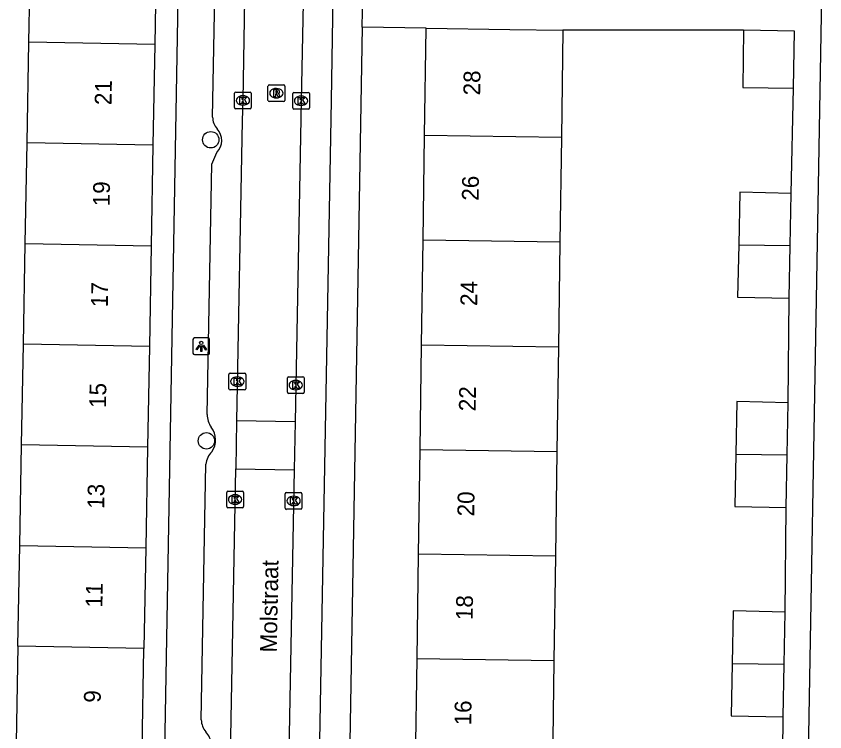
# Model space of a CAD drawing. Extents: x 160026 to 161302, y 384757 to 385701.
# Drawn here: x 160719.58 to 160767.81, y 385050.88 to 385093.54 of the extents above; entities that cross this region are included whole.
import ezdxf

# ---------------------------------------------------------------- set-up
doc = ezdxf.new("R2010")
doc.units = 0
for name, color, linetype in [('IMGEO_Boom', 7, 'Continuous'), ('IMGEO_Kolk', 7, 'Continuous'), ('IMGEO_Lichtpunt', 7, 'Continuous'), ('IMGEO_Openbare_ruimte_label', 7, 'Continuous'), ('IMGEO_Pand', 7, 'Continuous'), ('IMGEO_Pand_nummerreeks', 7, 'Continuous'), ('IMGEO_Rijbaan_lokaal_open', 7, 'Continuous'), ('IMGEO_Rioolput', 7, 'Continuous'), ('IMGEO_Voetpad_open', 7, 'Continuous')]:
    doc.layers.add(name, color=color, linetype=linetype)

msp = doc.modelspace()

# ---------------------------------------------------------------- linework, layer by layer
at = {"layer": 'IMGEO_Boom'}
for centre in [(160731.185, 385086.174), (160730.926, 385068.229)]:
    msp.add_circle(centre, 0.489, dxfattribs=at)
at = {"layer": 'IMGEO_Kolk'}
for p, q in [((160732.599, 385088.094), (160732.599, 385088.946)), ((160732.674, 385089.02), (160733.526, 385089.02)), ((160733.6, 385088.946), (160733.6, 385088.094)), ((160736.147, 385089.001), (160736.999, 385089.001)), ((160733.087, 385088.8), (160733.112, 385088.8)), ((160736.072, 385088.075), (160736.072, 385088.927)), ((160736.56, 385088.781), (160736.585, 385088.781)), ((160737.073, 385088.927), (160737.073, 385088.075)), ((160733.526, 385088.02), (160732.674, 385088.02)), ((160733.11, 385088.24), (160733.085, 385088.24)), ((160736.999, 385088.001), (160736.147, 385088.001)), ((160736.583, 385088.221), (160736.558, 385088.221)), ((160732.269, 385071.334), (160732.269, 385072.186)), ((160732.344, 385072.26), (160733.196, 385072.26)), ((160733.27, 385072.186), (160733.27, 385071.334)), ((160732.757, 385072.04), (160732.782, 385072.04)), ((160735.754, 385071.125), (160735.754, 385071.977)), ((160735.829, 385072.051), (160736.681, 385072.051)), ((160736.242, 385071.831), (160736.267, 385071.831)), ((160736.755, 385071.977), (160736.755, 385071.125)), ((160733.196, 385071.26), (160732.344, 385071.26)), ((160732.78, 385071.48), (160732.755, 385071.48)), ((160736.265, 385071.271), (160736.24, 385071.271)), ((160736.681, 385071.051), (160735.829, 385071.051)), ((160732.138, 385064.307), (160732.138, 385065.159)), ((160732.213, 385065.233), (160733.065, 385065.233)), ((160732.626, 385065.013), (160732.651, 385065.013)), ((160733.139, 385065.159), (160733.139, 385064.307)), ((160735.624, 385064.22), (160735.624, 385065.072)), ((160735.699, 385065.146), (160736.551, 385065.146)), ((160736.112, 385064.926), (160736.137, 385064.926)), ((160736.625, 385065.072), (160736.625, 385064.22)), ((160732.649, 385064.453), (160732.624, 385064.453)), ((160736.135, 385064.366), (160736.11, 385064.366)), ((160733.065, 385064.233), (160732.213, 385064.233)), ((160736.551, 385064.146), (160735.699, 385064.146))]:
    msp.add_line(p, q, dxfattribs=at)
for points in [[(160732.599, 385088.094), (160732.599, 385088.946)], [(160732.674, 385089.02), (160733.526, 385089.02)], [(160733.6, 385088.946), (160733.6, 385088.094)], [(160736.147, 385089.001), (160736.999, 385089.001)], [(160732.92, 385088.72), (160733.043, 385088.72), (160733.043, 385088.569), (160733.173, 385088.72), (160733.337, 385088.72), (160733.191, 385088.569), (160733.344, 385088.32), (160733.192, 385088.32), (160733.107, 385088.484), (160733.043, 385088.417), (160733.043, 385088.32), (160732.92, 385088.32), (160732.92, 385088.72)], [(160736.072, 385088.075), (160736.072, 385088.927)], [(160736.393, 385088.701), (160736.516, 385088.701), (160736.516, 385088.55), (160736.646, 385088.701), (160736.81, 385088.701), (160736.664, 385088.55), (160736.817, 385088.301), (160736.665, 385088.301), (160736.58, 385088.465), (160736.516, 385088.398), (160736.516, 385088.301), (160736.393, 385088.301), (160736.393, 385088.701)], [(160737.073, 385088.927), (160737.073, 385088.075)], [(160733.526, 385088.02), (160732.674, 385088.02)], [(160736.999, 385088.001), (160736.147, 385088.001)], [(160732.269, 385071.334), (160732.269, 385072.186)], [(160732.344, 385072.26), (160733.196, 385072.26)], [(160733.27, 385072.186), (160733.27, 385071.334)], [(160732.59, 385071.96), (160732.713, 385071.96), (160732.713, 385071.809), (160732.843, 385071.96), (160733.007, 385071.96), (160732.861, 385071.809), (160733.014, 385071.56), (160732.862, 385071.56), (160732.777, 385071.724), (160732.713, 385071.657), (160732.713, 385071.56), (160732.59, 385071.56), (160732.59, 385071.96)], [(160735.754, 385071.125), (160735.754, 385071.977)], [(160735.829, 385072.051), (160736.681, 385072.051)], [(160736.075, 385071.751), (160736.198, 385071.751), (160736.198, 385071.6), (160736.328, 385071.751), (160736.492, 385071.751), (160736.346, 385071.6), (160736.499, 385071.351), (160736.347, 385071.351), (160736.262, 385071.515), (160736.198, 385071.448), (160736.198, 385071.351), (160736.075, 385071.351), (160736.075, 385071.751)], [(160736.755, 385071.977), (160736.755, 385071.125)], [(160733.196, 385071.26), (160732.344, 385071.26)], [(160736.681, 385071.051), (160735.829, 385071.051)], [(160732.138, 385064.307), (160732.138, 385065.159)], [(160732.213, 385065.233), (160733.065, 385065.233)], [(160732.459, 385064.933), (160732.582, 385064.933), (160732.582, 385064.782), (160732.712, 385064.933), (160732.876, 385064.933), (160732.73, 385064.782), (160732.883, 385064.533), (160732.731, 385064.533), (160732.646, 385064.697), (160732.582, 385064.63), (160732.582, 385064.533), (160732.459, 385064.533), (160732.459, 385064.933)], [(160733.139, 385065.159), (160733.139, 385064.307)], [(160735.624, 385064.22), (160735.624, 385065.072)], [(160735.699, 385065.146), (160736.551, 385065.146)], [(160735.945, 385064.846), (160736.068, 385064.846), (160736.068, 385064.695), (160736.198, 385064.846), (160736.362, 385064.846), (160736.216, 385064.695), (160736.369, 385064.446), (160736.217, 385064.446), (160736.132, 385064.61), (160736.068, 385064.543), (160736.068, 385064.446), (160735.945, 385064.446), (160735.945, 385064.846)], [(160736.625, 385065.072), (160736.625, 385064.22)], [(160733.065, 385064.233), (160732.213, 385064.233)], [(160736.551, 385064.146), (160735.699, 385064.146)]]:
    msp.add_lwpolyline(points, dxfattribs=at)
for centre, start, end in [((160732.676, 385088.944), 91.552, 178.448), ((160732.676, 385088.944), 91.552, 178.448), ((160733.524, 385088.944), 1.552, 88.448), ((160733.524, 385088.944), 1.552, 88.448), ((160736.149, 385088.925), 91.552, 178.448), ((160736.149, 385088.925), 91.552, 178.448), ((160736.997, 385088.925), 1.552, 88.448), ((160736.997, 385088.925), 1.552, 88.448), ((160732.676, 385088.096), 181.552, 268.448), ((160732.676, 385088.096), 181.552, 268.448), ((160733.524, 385088.096), 271.552, 358.448), ((160733.524, 385088.096), 271.552, 358.448), ((160736.149, 385088.077), 181.552, 268.448), ((160736.149, 385088.077), 181.552, 268.448), ((160736.997, 385088.077), 271.552, 358.448), ((160736.997, 385088.077), 271.552, 358.448), ((160732.346, 385072.184), 91.552, 178.448), ((160732.346, 385072.184), 91.552, 178.448), ((160733.194, 385072.184), 1.552, 88.448), ((160733.194, 385072.184), 1.552, 88.448), ((160735.831, 385071.975), 91.552, 178.448), ((160735.831, 385071.975), 91.552, 178.448), ((160736.679, 385071.975), 1.552, 88.448), ((160736.679, 385071.975), 1.552, 88.448), ((160732.346, 385071.336), 181.552, 268.448), ((160732.346, 385071.336), 181.552, 268.448), ((160733.194, 385071.336), 271.552, 358.448), ((160733.194, 385071.336), 271.552, 358.448), ((160735.831, 385071.127), 181.552, 268.448), ((160735.831, 385071.127), 181.552, 268.448), ((160736.679, 385071.127), 271.552, 358.448), ((160736.679, 385071.127), 271.552, 358.448), ((160732.215, 385065.157), 91.552, 178.448), ((160732.215, 385065.157), 91.552, 178.448), ((160733.063, 385065.157), 1.552, 88.448), ((160733.063, 385065.157), 1.552, 88.448), ((160735.701, 385065.07), 91.552, 178.448), ((160735.701, 385065.07), 91.552, 178.448), ((160736.549, 385065.07), 1.552, 88.448), ((160736.549, 385065.07), 1.552, 88.448), ((160732.215, 385064.309), 181.552, 268.448), ((160732.215, 385064.309), 181.552, 268.448), ((160733.063, 385064.309), 271.552, 358.448), ((160733.063, 385064.309), 271.552, 358.448), ((160735.701, 385064.222), 181.552, 268.448), ((160735.701, 385064.222), 181.552, 268.448), ((160736.549, 385064.222), 271.552, 358.448), ((160736.549, 385064.222), 271.552, 358.448)]:
    msp.add_arc(centre, 0.0765, start, end, dxfattribs=at)
for centre, major_axis, ratio, start_param, end_param in [((160733.086, 385088.52), (-0.387, 0.002), 0.722429, 4.712389, 7.853982), ((160733.111, 385088.52), (-0.39, 0.002), 0.717154, 1.570796, 4.712389), ((160736.559, 385088.501), (-0.387, 0.002), 0.722429, 4.712389, 7.853982), ((160736.584, 385088.501), (-0.39, 0.002), 0.717154, 1.570796, 4.712389), ((160732.756, 385071.76), (-0.387, 0.002), 0.722429, 4.712389, 7.853982), ((160732.781, 385071.76), (-0.39, 0.002), 0.717154, 1.570796, 4.712389), ((160736.241, 385071.551), (-0.387, 0.002), 0.722429, 4.712389, 7.853982), ((160736.266, 385071.551), (-0.39, 0.002), 0.717154, 1.570796, 4.712389), ((160732.625, 385064.733), (-0.387, 0.002), 0.722429, 4.712389, 7.853982), ((160732.65, 385064.733), (-0.39, 0.002), 0.717154, 1.570796, 4.712389), ((160736.111, 385064.646), (-0.387, 0.002), 0.722429, 4.712389, 7.853982), ((160736.136, 385064.646), (-0.39, 0.002), 0.717154, 1.570796, 4.712389)]:
    msp.add_ellipse(centre, major_axis=major_axis, ratio=ratio, start_param=start_param, end_param=end_param, dxfattribs=at)
at = {"layer": 'IMGEO_Lichtpunt'}
for p, q in [((160730.12, 385074.27), (160730.12, 385073.463)), ((160730.12, 385074.27), (160730.12, 385073.463)), ((160731.022, 385074.365), (160730.214, 385074.365)), ((160731.022, 385074.365), (160730.214, 385074.365)), ((160731.116, 385073.463), (160731.116, 385074.27)), ((160731.116, 385073.463), (160731.116, 385074.27)), ((160730.214, 385073.369), (160731.022, 385073.369)), ((160730.214, 385073.369), (160731.022, 385073.369))]:
    msp.add_line(p, q, dxfattribs=at)
for points in [[(160730.494, 385073.934), (160730.533, 385073.906), (160730.345, 385073.644), (160730.307, 385073.671), (160730.494, 385073.934)], [(160730.596, 385073.886), (160730.643, 385073.886), (160730.643, 385073.564), (160730.596, 385073.564), (160730.596, 385073.886)], [(160730.706, 385073.906), (160730.744, 385073.933), (160730.931, 385073.671), (160730.892, 385073.643), (160730.706, 385073.906)]]:
    msp.add_lwpolyline(points, dxfattribs=at)
msp.add_circle((160730.619, 385074.068), 0.0994, dxfattribs=at)
for centre, start, end in [((160730.214, 385074.27), 90, 180), ((160730.214, 385074.27), 90, 180), ((160731.022, 385074.27), 0, 90), ((160731.022, 385074.27), 0, 90), ((160730.214, 385073.463), 180, 270), ((160730.214, 385073.463), 180, 270), ((160731.022, 385073.463), 270, 0), ((160731.022, 385073.463), 270, 360)]:
    msp.add_arc(centre, 0.0946, start, end, dxfattribs=at)
at = {"layer": 'IMGEO_Pand'}
for points in [[(160720.336, 385091.989), (160720.446, 385098.051)], [(160727.958, 385097.915), (160727.848, 385091.853)], [(160743.937, 385086.427), (160744.028, 385092.821)], [(160744.028, 385092.821), (160749.028, 385092.751), (160752.188, 385092.706)], [(160752.188, 385092.706), (160752.097, 385086.311)], [(160762.97, 385092.7), (160762.918, 385089.293), (160765.949, 385089.247)], [(160765.949, 385089.247), (160766.002, 385092.654), (160762.97, 385092.7)], [(160720.227, 385085.99), (160720.336, 385091.989)], [(160727.848, 385091.853), (160720.336, 385091.989)], [(160727.848, 385091.853), (160727.739, 385085.854)], [(160743.849, 385080.188), (160743.937, 385086.427)], [(160752.097, 385086.311), (160743.937, 385086.427)], [(160752.097, 385086.311), (160752.009, 385080.072)], [(160720.118, 385079.991), (160720.227, 385085.99)], [(160727.739, 385085.854), (160720.227, 385085.99)], [(160727.739, 385085.854), (160727.63, 385079.855)], [(160765.804, 385082.982), (160762.739, 385083.043), (160762.676, 385079.92)], [(160765.742, 385079.877), (160765.804, 385082.982)], [(160720.01, 385073.992), (160720.118, 385079.991)], [(160720.118, 385079.991), (160727.63, 385079.855)], [(160727.63, 385079.855), (160727.522, 385073.856)], [(160743.76, 385073.949), (160743.849, 385080.188)], [(160752.009, 385080.072), (160743.849, 385080.188)], [(160752.009, 385080.072), (160751.92, 385073.833)], [(160762.676, 385079.92), (160762.614, 385076.794), (160765.679, 385076.733)], [(160762.676, 385079.92), (160765.742, 385079.877)], [(160765.679, 385076.733), (160765.742, 385079.877)], [(160719.901, 385067.993), (160720.01, 385073.992)], [(160727.522, 385073.856), (160720.01, 385073.992)], [(160727.522, 385073.856), (160727.413, 385067.857)], [(160743.672, 385067.709), (160743.76, 385073.949)], [(160743.76, 385073.949), (160751.92, 385073.833)], [(160751.92, 385073.833), (160751.831, 385067.593)], [(160765.626, 385070.503), (160762.566, 385070.564), (160762.503, 385067.441)], [(160765.564, 385067.398), (160765.626, 385070.503)], [(160719.792, 385061.994), (160719.901, 385067.993)], [(160727.413, 385067.857), (160719.901, 385067.993)], [(160727.413, 385067.857), (160727.304, 385061.858)], [(160743.583, 385061.47), (160743.672, 385067.709)], [(160743.672, 385067.709), (160751.831, 385067.593)], [(160751.831, 385067.593), (160751.743, 385061.354)], [(160762.503, 385067.441), (160762.441, 385064.315), (160765.501, 385064.254)], [(160762.503, 385067.441), (160765.564, 385067.398)], [(160765.501, 385064.254), (160765.564, 385067.398)], [(160719.683, 385055.994), (160719.792, 385061.994)], [(160719.792, 385061.994), (160727.304, 385061.858)], [(160727.304, 385061.858), (160727.195, 385055.858)], [(160743.495, 385055.23), (160743.583, 385061.47)], [(160751.743, 385061.354), (160743.583, 385061.47)], [(160751.743, 385061.354), (160751.654, 385055.114)], [(160765.449, 385058.024), (160762.343, 385058.086), (160762.28, 385054.963)], [(160765.387, 385054.919), (160765.449, 385058.024)], [(160719.683, 385055.994), (160719.578, 385050.238)], [(160727.195, 385055.858), (160719.683, 385055.994)], [(160727.086, 385049.859), (160727.195, 385055.858)], [(160743.406, 385048.991), (160743.495, 385055.23)], [(160751.654, 385055.114), (160743.495, 385055.23)], [(160751.654, 385055.114), (160751.565, 385048.875)], [(160762.28, 385054.963), (160762.218, 385051.837), (160765.324, 385051.775)], [(160762.28, 385054.963), (160765.387, 385054.919)], [(160765.324, 385051.775), (160765.387, 385054.919)]]:
    msp.add_lwpolyline(points, dxfattribs=at)
at = {"layer": 'IMGEO_Rijbaan_lokaal_open'}
for points in [[(160733.775, 385129.412), (160733.102, 385088.536), (160733.061, 385087.306), (160732.728, 385069.429)], [(160737.344, 385129.396), (160737.293, 385126.916), (160736.927, 385106.07), (160736.576, 385088.501), (160736.216, 385069.362)], [(160765.809, 384990.866), (160767.813, 385104.916)], [(160732.728, 385069.429), (160732.674, 385066.559)], [(160736.216, 385069.362), (160732.728, 385069.429)], [(160736.216, 385069.362), (160736.162, 385066.492)], [(160731.463, 385001.565), (160732.674, 385066.559)], [(160732.674, 385066.559), (160736.162, 385066.492)], [(160736.162, 385066.492), (160734.935, 385001.318)]]:
    msp.add_lwpolyline(points, dxfattribs=at)
at = {"layer": 'IMGEO_Rioolput'}
for p, q in [((160734.674, 385089.452), (160735.526, 385089.452)), ((160734.599, 385088.526), (160734.599, 385089.378)), ((160735.087, 385089.232), (160735.112, 385089.232)), ((160735.6, 385089.378), (160735.6, 385088.526)), ((160735.11, 385088.672), (160735.085, 385088.672)), ((160735.526, 385088.452), (160734.674, 385088.452))]:
    msp.add_line(p, q, dxfattribs=at)
for points in [[(160734.674, 385089.452), (160735.526, 385089.452)], [(160734.599, 385088.526), (160734.599, 385089.378)], [(160735.188, 385089.15), (160734.936, 385089.152), (160734.936, 385088.752)], [(160735.114, 385089.071), (160735.06, 385089.071), (160735.06, 385088.99)], [(160735.06, 385088.99), (160735.112, 385088.99)], [(160735.6, 385089.378), (160735.6, 385088.526)], [(160734.936, 385088.752), (160735.06, 385088.752), (160735.06, 385088.914), (160735.071, 385088.914)], [(160735.118, 385088.885), (160735.189, 385088.752), (160735.329, 385088.752), (160735.264, 385088.878)], [(160735.526, 385088.452), (160734.674, 385088.452)]]:
    msp.add_lwpolyline(points, dxfattribs=at)
for centre, radius, start, end in [((160734.676, 385089.376), 0.0765, 91.552, 178.448), ((160734.676, 385089.376), 0.0765, 91.552, 178.448), ((160735.524, 385089.376), 0.0765, 1.552, 88.448), ((160735.524, 385089.376), 0.0765, 1.552, 88.448), ((160735.096, 385089.179), 0.19, 274.7715, 282.9687), ((160735.12, 385088.975), 0.0964, 77.0061, 93.1865), ((160735.134, 385089.032), 0.0378, 276.6634, 79.6772), ((160735.187, 385089.04), 0.109, 350.3612, 89.416), ((160735.185, 385089.04), 0.112, 277.5842, 350.9817), ((160734.676, 385088.528), 0.0765, 181.552, 268.448), ((160734.676, 385088.528), 0.0765, 181.552, 268.448), ((160735.07, 385088.861), 0.0533, 26.0293, 88.6989), ((160735.169, 385088.825), 0.108, 29.5134, 73.7905), ((160735.524, 385088.528), 0.0765, 271.552, 358.448), ((160735.524, 385088.528), 0.0765, 271.552, 358.448)]:
    msp.add_arc(centre, radius, start, end, dxfattribs=at)
for centre, major_axis, ratio, start_param, end_param in [((160735.086, 385088.952), (-0.387, 0.002), 0.722429, 4.712389, 7.853982), ((160735.111, 385088.952), (-0.39, 0.002), 0.717154, 1.570796, 4.712389)]:
    msp.add_ellipse(centre, major_axis=major_axis, ratio=ratio, start_param=start_param, end_param=end_param, dxfattribs=at)
at = {"layer": 'IMGEO_Voetpad_open'}
for points in [[(160727.96, 385022.845), (160729.292, 385097.92), (160727.958, 385097.915)], [(160731.297, 385087.53), (160731.484, 385097.845)], [(160740.222, 385092.887), (160740.272, 385095.767)], [(160738.469, 385094.718), (160738.369, 385088.517), (160737.671, 385050.34)], [(160740.222, 385092.887), (160739.245, 385036.428)], [(160744.028, 385092.821), (160740.222, 385092.887)], [(160762.97, 385092.7), (160752.188, 385092.706)], [(160765.804, 385082.982), (160765.949, 385089.247)], [(160730.961, 385069.797), (160731.24, 385084.72), (160731.54, 385085.421)], [(160765.626, 385070.503), (160765.679, 385076.733)], [(160730.615, 385051.589), (160730.884, 385066.829)], [(160765.449, 385058.024), (160765.501, 385064.254)], [(160765.272, 385045.546), (160765.324, 385051.775)]]:
    msp.add_lwpolyline(points, dxfattribs=at)
for centre, radius, start, end in [((160732.334, 385087.523), 1.037, 179.6124, 222.3864), ((160730.83, 385086.137), 1.009, 314.7763, 42.937), ((160732.48, 385069.877), 1.521, 183.0182, 213.397), ((160730.261, 385068.287), 1.212, 324.4893, 38.4201), ((160732.172, 385066.673), 1.297, 135.4766, 173.108), ((160731.813, 385051.652), 1.2, 182.9892, 219.7704), ((160730.16, 385050.158), 1.03, 0.427, 44.79)]:
    msp.add_arc(centre, radius, start, end, dxfattribs=at)

# ---------------------------------------------------------------- texts
at = {"layer": 'IMGEO_Openbare_ruimte_label'}
msp.add_text('Molstraat', height=1, rotation=88.9115, dxfattribs=at).set_placement((160735.123, 385055.606))
at = {"layer": 'IMGEO_Pand_nummerreeks'}
for s, rotation, p in [('28', 89.1872, (160747.252, 385088.814)), ('21', 88.9609, (160725.262, 385088.233)), ('26', 89.1872, (160747.163, 385082.538)), ('19', 88.9609, (160725.152, 385082.201)), ('17', 88.9609, (160725.043, 385076.191)), ('24', 89.1872, (160747.074, 385076.264)), ('15', 88.9609, (160724.934, 385070.182)), ('22', 89.1872, (160746.985, 385069.987)), ('13', 88.9609, (160724.825, 385064.172)), ('20', 89.1872, (160746.896, 385063.72)), ('11', 88.9609, (160724.718, 385058.276)), ('18', 89.1872, (160746.808, 385057.537)), ('9', 88.9632, (160724.616, 385052.612)), ('16', 89.1872, (160746.719, 385051.261))]:
    msp.add_text(s, height=1, rotation=rotation, dxfattribs=at).set_placement(p)

doc.saveas('drawing.dxf')
